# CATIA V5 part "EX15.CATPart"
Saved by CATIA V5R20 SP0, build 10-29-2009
Part number: EX15
Bounding box of the stored display mesh (mm): x -99.5 to 72.5, y -25.994 to 26, z 0 to 10
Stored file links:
  E:\Nouveau dossier\tarek\mécaniquee\Catia\TP 0\EX15.CATPart
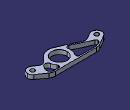
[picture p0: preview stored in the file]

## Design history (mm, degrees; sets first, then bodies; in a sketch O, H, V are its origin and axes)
Set1
  DatumSurface1 to DatumSurface40
Body1 (main body)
